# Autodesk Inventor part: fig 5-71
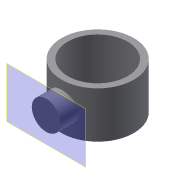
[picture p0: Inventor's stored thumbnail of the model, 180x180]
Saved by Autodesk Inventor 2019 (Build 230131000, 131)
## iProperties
Shininess: 64.0
Length Units: 11269
Angle Units: 11279
Time Units: 11290
Mass Units: 11283
Length Display Precision: 3
Angle Display Precision: 2
Compacted: True
Part Number: fig 5-71
Document SubType Name: Modeling
Created: 2002-12
Designer: deepak
Density: 1 g/cm^3
Material: Generic
Appearance: Default
Density: 0.0
Volumn: 0.0
Area: 0.0
PropertySet Name: Model Information
Control State: 0
Master: False
Checked Out: False
Author: deepak
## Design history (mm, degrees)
sketch "Sketch1"
  geometry: C1 r 23.454 at (0, 0); C2 r 19.43 at (0, 0)
  constraints: 2 centre point, 1 coincident, 1 concentric
extrude "Extrusion1" new body sketch "Sketch1" stored distance "d0" = 30; taper "d1" = 0 deg
workplane "Work Plane1"
workplane "Work Plane2"
sketch "Sketch2"
  geometry: C1 r 9.343 at (0, 0)
  constraints: 1 centre point
extrude "Extrusion2" join sketch "Sketch2" stored distance "d4" = 10; taper "d5" = 0 deg
body "Solid1"
